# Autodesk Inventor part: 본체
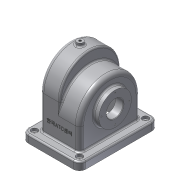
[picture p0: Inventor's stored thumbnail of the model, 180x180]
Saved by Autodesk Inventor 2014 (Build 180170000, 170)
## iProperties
Created: 2017-11
Part Number: 본체
Material: 알루미늄 6061
Document SubType Name: Modeling
Designer: user
Density: 2.71 g/cm^3
Appearance: 알루미늄 - 평지
Mass: 1079.2 g
Surface Area: 1187.1 cm^2
Volume: 398.23 cm^3
Author: user
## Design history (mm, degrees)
sketch "스케치1"
  geometry: L1 (55, 75)-(-55, 75); L2 (-55, 75)-(-55, -75); L3 (-55, -75)-(55, -75); L4 (55, -75)-(55, 75); L5 (55, 75)-(-55, -75); L6 (-55, 75)-(55, -75); 1 further point
  constraints: 12 end point, 2 midpoint, 2 parallel, 1 horizontal, 1 perpendicular
  dimensions: "d0" = 110 distance of L2.end L3.end; "d1" = 150 distance of L1.end L2.end
extrude "돌출1" new body sketch "스케치1" distance "d2" = 15; taper "d3" = 0 deg
sketch "스케치3"
  geometry: L1 (15, -75)-(15, 75) reference; L2 (0, -75)-(0, 75) reference; L3 (80, 58)-(15, 58); L4 (80, -58)-(15, -58); L5 (15, 58)-(15, -58); A1 r 58 centre (80, 0) between (80, -58) and (80, 58); 1 further point
  constraints: 6 end point, 2 perpendicular, 2 point on circle, 2 point on line, 2 tangent, 1 centre point, 1 collinear
  dimensions: "d4" = 116 diameter of A1; "d5" = 80 distance from line of L2 A1.centre
extrude "돌출2" join sketch "스케치3" distance "d6" = 38; taper "d7" = 0 deg
sketch "스케치4"
  geometry: L1 (-75, 0)-(75, 0) reference; C1 r 37.5 at (0, 65); A1 r 58 centre (0, 80) between (58, 80) and (-58, 80) reference; 1 further point
  constraints: 1 centre point, 1 vertical alignment
  dimensions: "d8" = 75 diameter of C1; "d9" = 65 distance from line of L1 C1.centre
extrude "돌출3" join sketch "스케치4" distance "d10" = 9; taper "d11" = 0 deg
sketch "스케치5"
  geometry: L1 (-58, 15)-(-58, 80) reference; L2 (58, 15)-(-58, 15) reference; L3 (58, 80)-(58, 15) reference; L4 (-75, 0)-(75, 0) reference; L5 (-58, 57)-(-58, 15); L6 (58, 57)-(58, 15); L7 (-58, 15)-(58, 15); A1 r 58 centre (0, 80) between (58, 80) and (-58, 80) reference; A2 r 58 centre (0, 57) between (58, 57) and (-58, 57); 1 further point
  constraints: 6 end point, 2 point on circle, 2 point on line, 1 centre point, 1 collinear, 1 parallel, 1 perpendicular, 1 tangent, 1 vertical alignment
  dimensions: "d13" = 57 distance from line of L4 A2.centre
extrude "돌출4" join sketch "스케치5" distance "d14" = 38; taper "d15" = 0 deg
sketch "스케치6"
  geometry: L1 (-75, 0)-(75, 0) reference; C1 r 31 at (0, 65); A1 r 58 centre (0, 57) between (58, 57) and (-58, 57) reference; 1 further point
  constraints: 1 centre point, 1 vertical alignment
  dimensions: "d16" = 62 diameter of C1; "d17" = 65 distance from line of L1 C1.centre
extrude "돌출5" join sketch "스케치6" distance "d18" = 10; taper "d19" = 0 deg
node "작업 평면1"
sketch "스케치7"
  geometry: L1 (-53, 80)-(-53, 0); L2 (-53, 0)-(53, 0); L3 (53, 0)-(53, 80); L4 (75, 0)-(-75, 0) reference; A1 r 58 centre (0, 80) between (58, 80) and (-58, 80) reference; A2 r 53 centre (0, 80) between (53, 80) and (-53, 80); 1 further point
  constraints: 6 end point, 2 point on circle, 2 tangent, 1 centre point, 1 collinear, 1 parallel, 1 perpendicular, 1 vertical
  dimensions: "d21" = 5 radial gap between concentric circles of A2 A1
extrude "돌출6" cut sketch "스케치7" distance "d22" = 28; taper "d23" = 0 deg
node "작업 평면2"
sketch "스케치9"
  geometry: L1 (-53, 0)-(53, 0) reference; L2 (-53, 57)-(-53, 0); L3 (53, 57)-(53, 0); L4 (-53, 0)-(53, 0); A1 r 58 centre (0, 57) between (58, 57) and (-58, 57) reference; A2 r 53 centre (0, 57) between (53, 57) and (-53, 57); 1 further point
  constraints: 6 end point, 2 point on circle, 2 tangent, 1 centre point, 1 collinear
  dimensions: "d25" = 5 radial gap between concentric circles of A2 A1
extrude "돌출7" cut sketch "스케치9" stored distance "d26" = 28; taper "d27" = 0 deg
fillet "모깎기1" dims "d28" = 3
hole "구멍1" diameter "d31" = 32; stored, may be unused: countersink angle "d35" = 90 deg, drill point angle "d37" = 118 deg; dims "d29" = 10, "d30" = 10, "d32" = 6, "d33" = 4, "d34" = 2, "d36" = 8
chamfer "모따기1" distance "d38" = 1; stored, may be unused: second distance "d39" = 2, angle "d40" = 45 deg
node "작업 평면3"
sketch "스케치10"
  geometry: L1 (0, -58)-(-38, -58) reference; L2 (55, -75)-(-55, -75) reference; L3 (-38, 58)-(-38, -58) reference; C1 r 6 at (-19, 0); 1 further point
  constraints: 1 centre point
  dimensions: "d42" = 12 diameter of C1; "d44" = 75 distance from line of L2 C1.centre; "d45" = 19 distance from line of L3 C1.centre
extrude "돌출8" join sketch "스케치10" stored distance "d46" = 28; taper "d47" = 0 deg
hole "구멍2" diameter "d50" = 4.459; stored, may be unused: countersink angle "d54" = 90 deg, drill point angle "d56" = 118 deg; dims "d51" = 15, "d52" = 4, "d53" = 2, "d55" = 8, "d107" = 10, "d108" = 10
fillet "모깎기2" dims "d58" = 3
fillet "모깎기3" dims "d59" = 8
fillet "모깎기4" dims "d60" = 12
hole "구멍3" diameter "d63" = 5; stored, may be unused: countersink angle "d67" = 90 deg, drill point angle "d69" = 118 deg; dims "d61" = 10, "d62" = 10, "d64" = 5, "d65" = 12, "d66" = 5, "d68" = 8
hole "구멍4" diameter "d72" = 5; stored, may be unused: countersink angle "d76" = 90 deg, drill point angle "d78" = 118 deg; dims "d70" = 10, "d71" = 10, "d73" = 5, "d74" = 12, "d75" = 5, "d77" = 8
fillet "모깎기5" dims "d79" = 3
sketch "스케치11"
  geometry: C1 r 37.5 at (0, 0) reference; 2 further points
  constraints: 1 vertical alignment
  dimensions: "d80" = 29 distance of C1.centre point (0, 29)
hole "구멍5" sketch "스케치11" at (0, 29) diameter "d81" = 2.459; stored, may be unused: countersink angle "d85" = 90 deg, drill point angle "d87" = 118 deg; dims "d82" = 6, "d83" = 12, "d84" = 5, "d86" = 8
sketch "스케치12"
  geometry: C1 r 31 at (0, 0) reference; 2 further points
  constraints: 1 vertical alignment
  dimensions: "d91" = 26 distance of point (0, 26) C1.centre
hole "구멍6" sketch "스케치12" at (0, 26) diameter "d92" = 2.459; stored, may be unused: countersink angle "d96" = 90 deg, drill point angle "d98" = 118 deg; dims "d93" = 6, "d94" = 12, "d95" = 5, "d97" = 8
sketch "스케치13"
  geometry: L1 (-40, -57)-(46, -57) reference; L2 (-35, 23)-(-35, -39) reference; 2 further points
  constraints: 1 other
  dimensions: "d102" = 40 distance from line of L1 point (3, -17); "d103" = 38 distance from line of L2 point (3, -17)
feature "엠보싱1" sketch "스케치13" dims "d0" = 110, "d1" = 150, "d8" = 75, "d9" = 65, "d104" = 0.5, "d105" = 0
fillet "모깎기6" dims "d106" = 3
node "솔리드1"
mirror "대칭1"
pattern_circular "원형 패턴1" dims angle "d89" = 360 deg
pattern_circular "원형 패턴2" dims angle "d100" = 360 deg
other parameters: "d12" = 116, "d20" = -5, "d24" = -5, "d41" = -144
